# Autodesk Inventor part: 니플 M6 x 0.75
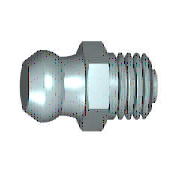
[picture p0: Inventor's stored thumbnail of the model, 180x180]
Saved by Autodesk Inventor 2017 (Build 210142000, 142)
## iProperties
IsCustomPart: 1
Created: 2012-02
Part Number: 니플 M6 x 0.75
Material: 강철, 연강
Description: 윤활 니플, 원추 유형 A
Document SubType Name: Modeling
Standard: JIS B 1575
Designer: mduedu
Standards Organization: JIS
Language: ko-KR
Size Designation: MT 6 x 0.75
Categories: <MemberInstance><Categories><Category DisplayName="기타 부품" InternalName="5aa15e00-363f-49f2-933f-16f664388e3f" Mnemonic="OTHER"><Category DisplayName="그리스 부속품" I
Density: 7.86 g/cm^3
Mass: 3.2546 g
Surface Area: 3.29319 cm^2
Volume: 0.414071 cm^3
Appearance: 금색
Author: mduedu
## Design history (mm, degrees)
sketch "스케치1"
  geometry: L1 (-8.8, 0)-(-8.8, 2.4); L2 (-8.8, 2.4)-(-7.335, 3.202); L3 (-8.8, 0)-(4.7, 0); L4 (4.7, 0)-(4.7, 1.5); L5 (4.7, 1.5)-(4, 1.5); L6 (4, 1.5)-(4, 3); L7 (4, 3)-(0, 3); L8 (-11.5, 0)-(7.4, 0) reference; L9 (0, -1.733)-(0, 10.398) reference; L10 (-3, 3.5)-(0, 3.5); L11 (0, 3.5)-(0, 3); A1 r 3.3 centre (-6.535, 0) between (-4.789, 2.8) and (-7.335, 3.202); A2 r 6 centre (-6.053, 8.665) between (-4.789, 2.8) and (-3, 3.5)
  constraints: 18 end point, 5 perpendicular, 4 point on circle, 2 centre point, 2 parallel, 2 point on line, 1 collinear, 1 vertical
  dimensions: "d0" = 13.5 distance between parallel lines of L1 L4 (= GL); "d1" = 5.6 diameter of A1.start L3 (= KGB2); "d2" = 0.7 distance between parallel lines of L4 L6 (= PHH); "d3" = 3 diameter of L5 L3 (= 0.5 x NND); "d4" = 6 diameter of L7 L3 (= NND); "d5" = 6.6 dimension on A1 L3 (= KR); "d6" = 4.8 diameter of L1.end L3 (= KGB1); "d7" = 6 radius of A2 (= RBN); "d11" = 7 diameter of L10.start L3 (= SW); "d14" = 3 distance of L10.start L10.end (= KOH); "d15" = 4 distance between parallel lines of L6 L11 (= NLG); "d61" = 7.33505 distance from line of L9 L2.end (computed from KGB1, KR, PHH, GL, NLG, VERS); "d62" = 6.53505 distance from line of L9 A1.centre (computed from NLG, GL, PHH, KR, KGB1)
revolve "본체" sketch "스케치1" stored, may be unused: angle "d25" = 90 deg
sketch "스케치2"
  geometry: L1 (2.021, 3.5)-(4.041, 0); L2 (4.041, 0)-(2.021, -3.5); L3 (2.021, -3.5)-(-2.021, -3.5); L4 (-2.021, -3.5)-(-4.041, 0); L5 (-4.041, 0)-(-2.021, 3.5); L6 (-2.021, 3.5)-(2.021, 3.5); C1 r 3.5 at (0, 0) reference; 1 further point
  constraints: 12 end point, 1 coincident, 1 horizontal, 1 tangent, 11 other
extrude "머리" join sketch "스케치2" distance "d17" = 3 (= KOH); taper "d18" = 0 deg
sketch "스케치3"
  geometry: L1 (2.687, 4.041)-(3, 4.041); L2 (3, 4.041)-(3, 3.5); L3 (3, 3.5)-(2.687, 4.041); L4 (0.313, 4.041)-(0, 4.041); L5 (0, 4.041)-(0, 3.5); L6 (0, 3.5)-(0.313, 4.041); L7 (3.6, 0)-(-0.6, 0) reference; L8 (0, 4.041)-(0, 2.021) reference; L9 (0, 4.041)-(3, 4.041) reference; L10 (3, 3.031)-(3, 4.041) reference
  constraints: 12 end point, 4 collinear, 3 perpendicular, 1 horizontal
  dimensions: "d19" = 3.5 distance from line of L5.end L7 (= 0.5 x SW); "d20" = 3.5 distance from line of L2.end L7 (= 0.5 x SW); "d21" = 30 deg angle of L6 L5; "d22" = 30 deg angle of L2 L3
revolve "모따기1" sketch "스케치3" stored, may be unused: angle "d56" = 90 deg
body "Solid1"
fillet "모깎기1" dims "d8" = 0.2 (= RR)
feature "스레드1" dims "d9" = 3.53991 (= NLG - GAL), "d10" = 0
chamfer "모따기2" distance "d23" = 0.46009 (= -0.5 x GD1 + 0.5 x NND); stored, may be unused: angle "d24" = 45 deg, second distance "d59" = 0.46009 (= -0.5 x GD1 + 0.5 x NND)
other parameters: "NLG" = 4 [user parameter; used in 4 equation terms], "GL" = 13.5 [user parameter; used in 3 equation terms], "NND" = 6 [user parameter; used in 4 equation terms], "KGB1" = 4.8 [user parameter; used in 3 equation terms], "KGB2" = 5.6 [user parameter; used in 1 equation term], "VERS" = 0.8 [user parameter; used in 1 equation term], "KR" = 6.6 [user parameter; used in 3 equation terms], "RBN" = 6 [user parameter; used in 1 equation term], "SW" = 7 [user parameter; used in 3 equation terms], "KOH" = 3 [user parameter; used in 2 equation terms], "GAL" = 0.46009 (= 0.61345 x PTC) [user parameter; used in 1 equation term], "FAWI" = 45 deg [user parameter], "PHH" = 0.7 [user parameter; used in 3 equation terms], "GD1" = 5.07983 (= THREADDIA - 1.2269 x PTC) [user parameter; used in 2 equation terms], "RR" = 0.2 [user parameter; used in 1 equation term], "d12" = 0, "d13" = 0, "GUL" = 0.46009 (= 0.61345 x PTC) [user parameter], "TPU" = 13.33333 (computed from PTC) [user parameter], "DULO" = 1.5 [user parameter], "PTC" = 0.75 [user parameter; used in 4 equation terms], "GEL" = 4 [user parameter], "THREADDIA" = 6 [user parameter; used in 1 equation term], "TOA" = 30 deg [user parameter]
